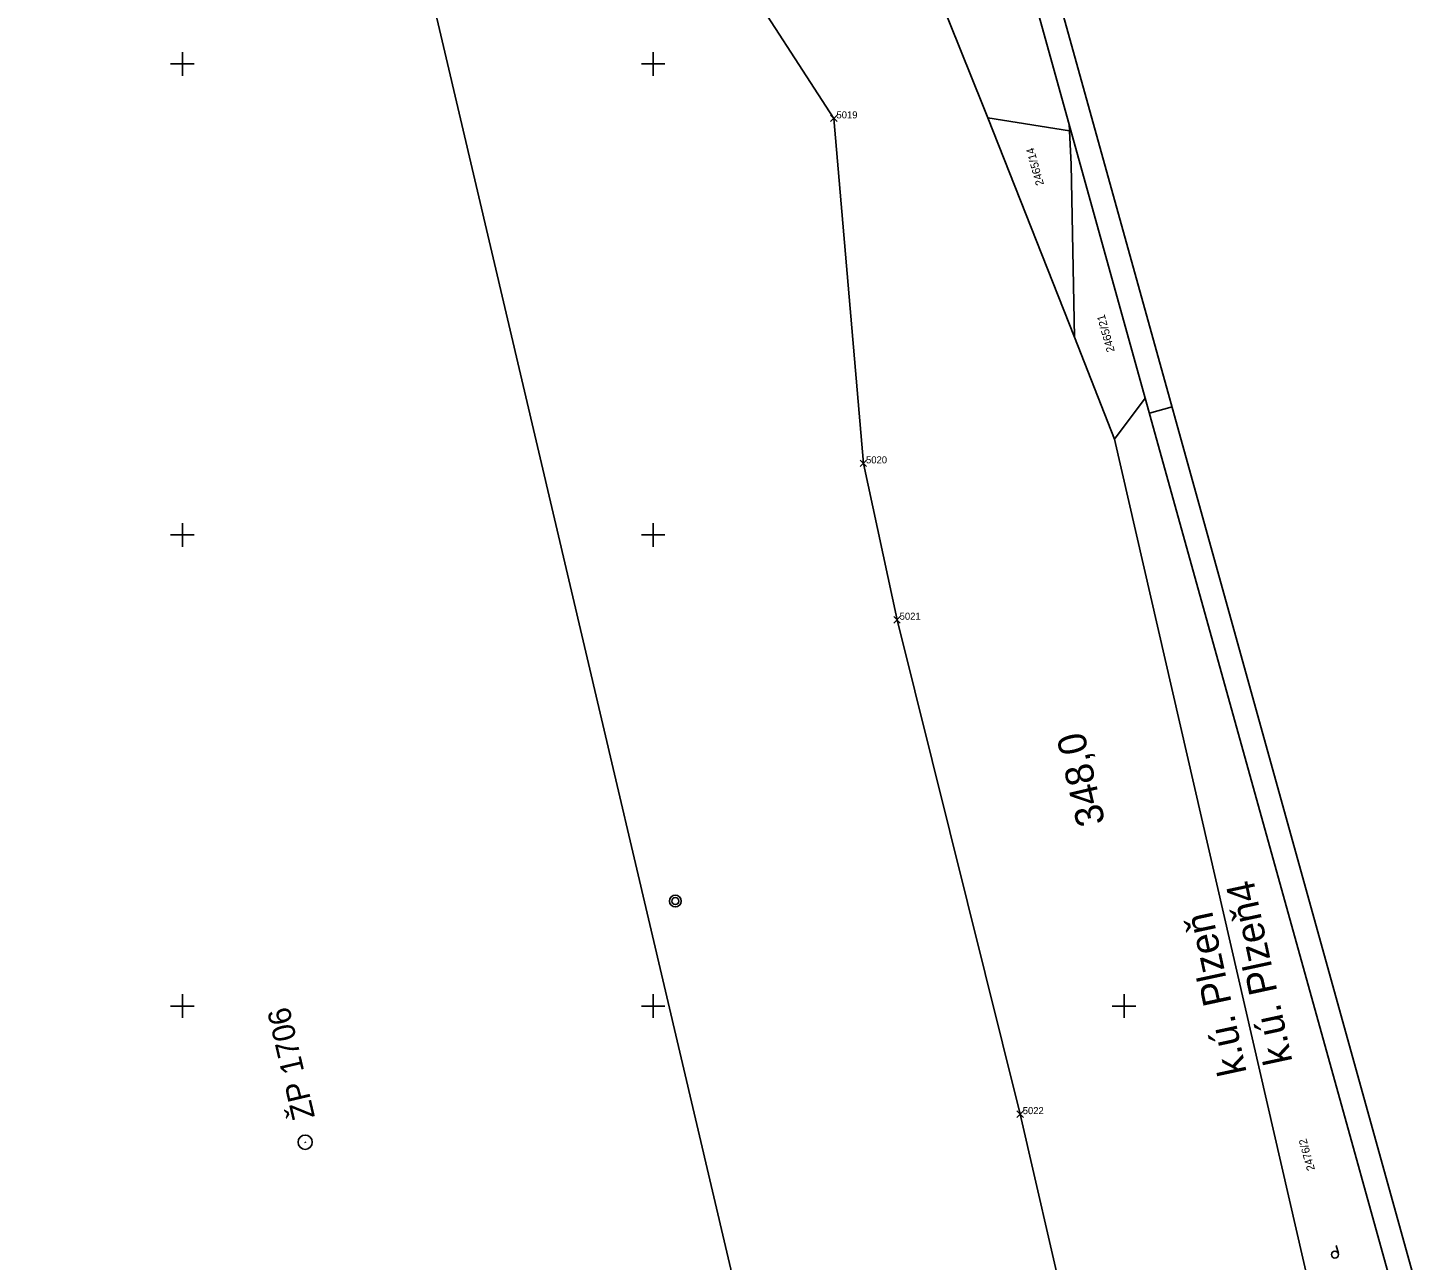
# Model space of a CAD drawing. Extents: x -821172 to -820632, y -1070921 to -1069931.
# Drawn here: x -820866.4 to -820719.1, y -1070527 to -1070396.2 of the extents above; entities that cross this region are included whole.
import ezdxf

# ---------------------------------------------------------------- set-up
doc = ezdxf.new("R2010")
doc.units = 0
for name, color, linetype in [('Ram', 7, 'Continuous'), ('Sit', 7, 'Continuous'), ('Sttaniceni a namezniky', 7, 'Continuous'), ('VB_bod_DZ', 7, 'Continuous'), ('Vrstva 52', 7, 'Continuous'), ('Vrstva 53', 7, 'Continuous'), ('Vrstva 55', 7, 'Continuous'), ('Vrstva 57', 7, 'Continuous'), ('Vrstva 59', 7, 'Continuous'), ('ZBP', 7, 'Continuous')]:
    doc.layers.add(name, color=color, linetype=linetype)

msp = doc.modelspace()

# ---------------------------------------------------------------- linework, layer by layer
at = {"layer": 'Ram'}
msp.add_line((-820744.9, -1070436.39), (-820747.31, -1070437.06), dxfattribs=at)
for points in [[(-820857.35, -1070031.72), (-820632.46, -1070841.06)], [(-820859.09, -1070034.8), (-820635.54, -1070839.32), (-820916.88, -1070917.49)]]:
    msp.add_lwpolyline(points, dxfattribs=at)
at = {"layer": 'Sit'}
for p, q in [((-820850, -1070398.75), (-820850, -1070400)), ((-820800, -1070398.75), (-820800, -1070400)), ((-820851.25, -1070400), (-820850, -1070400)), ((-820848.75, -1070400), (-820850, -1070400)), ((-820850, -1070401.25), (-820850, -1070400)), ((-820801.25, -1070400), (-820800, -1070400)), ((-820798.75, -1070400), (-820800, -1070400)), ((-820800, -1070401.25), (-820800, -1070400)), ((-820850, -1070448.75), (-820850, -1070450)), ((-820800, -1070448.75), (-820800, -1070450)), ((-820851.25, -1070450), (-820850, -1070450)), ((-820848.75, -1070450), (-820850, -1070450)), ((-820850, -1070451.25), (-820850, -1070450)), ((-820801.25, -1070450), (-820800, -1070450)), ((-820798.75, -1070450), (-820800, -1070450)), ((-820800, -1070451.25), (-820800, -1070450)), ((-820850, -1070498.75), (-820850, -1070500)), ((-820800, -1070498.75), (-820800, -1070500)), ((-820750, -1070498.75), (-820750, -1070500)), ((-820851.25, -1070500), (-820850, -1070500)), ((-820848.75, -1070500), (-820850, -1070500)), ((-820850, -1070501.25), (-820850, -1070500)), ((-820801.25, -1070500), (-820800, -1070500)), ((-820798.75, -1070500), (-820800, -1070500)), ((-820800, -1070501.25), (-820800, -1070500)), ((-820751.25, -1070500), (-820750, -1070500)), ((-820748.75, -1070500), (-820750, -1070500)), ((-820750, -1070501.25), (-820750, -1070500))]:
    msp.add_line(p, q, dxfattribs=at)
at = {"layer": 'Sttaniceni a namezniky'}
for radius in [0.623, 0.376]:
    msp.add_circle((-820797.65, -1070488.86), radius, dxfattribs=at)
at = {"layer": 'VB_bod_DZ'}
for p, q in [((-820781.17, -1070406.12), (-820780.48, -1070405.43)), ((-820780.48, -1070406.12), (-820781.17, -1070405.43)), ((-820778.03, -1070442.74), (-820777.34, -1070442.05)), ((-820777.34, -1070442.74), (-820778.03, -1070442.05)), ((-820774.45, -1070459.35), (-820773.76, -1070458.66)), ((-820773.76, -1070459.35), (-820774.45, -1070458.66)), ((-820761.38, -1070511.82), (-820760.69, -1070511.13)), ((-820760.69, -1070511.82), (-820761.38, -1070511.13))]:
    msp.add_line(p, q, dxfattribs=at)
at = {"layer": 'Vrstva 52'}
for points in [[(-820791.18, -1070389.77), (-820780.82, -1070405.78), (-820777.68, -1070442.4), (-820774.11, -1070459), (-820761.04, -1070511.47), (-820756.27, -1070532.22), (-820758.47, -1070564.86)], [(-820782.06, -1070569.19), (-820823.93, -1070391.03)]]:
    msp.add_lwpolyline(points, dxfattribs=at)
at = {"layer": 'Vrstva 53'}
for p, q in [((-820780.16, -1070366.62), (-820765.05, -1070404.29)), ((-820765.05, -1070404.29), (-820764.48, -1070405.73)), ((-820764.48, -1070405.73), (-820755.27, -1070429)), ((-820755.27, -1070429), (-820751, -1070439.83)), ((-820751, -1070439.83), (-820721.42, -1070568.42))]:
    msp.add_line(p, q, dxfattribs=at)
at = {"layer": 'Vrstva 55'}
for p, q in [((-820765.05, -1070404.29), (-820780.16, -1070366.62)), ((-820764.48, -1070405.73), (-820765.05, -1070404.29)), ((-820755.27, -1070429), (-820764.48, -1070405.73)), ((-820764.48, -1070405.73), (-820755.8, -1070407.09)), ((-820755.8, -1070407.09), (-820755.83, -1070406.39)), ((-820751, -1070439.83), (-820755.27, -1070429)), ((-820751, -1070439.83), (-820747.75, -1070435.47)), ((-820721.42, -1070568.42), (-820751, -1070439.83))]:
    msp.add_line(p, q, dxfattribs=at)
msp.add_lwpolyline([(-820755.27, -1070429), (-820755.62, -1070410.67), (-820755.8, -1070407.09)], dxfattribs=at)
at = {"layer": 'Vrstva 59'}
msp.add_line((-820727.24, -1070526.29), (-820727.47, -1070525.44), dxfattribs=at)
msp.add_circle((-820727.61, -1070526.39), 0.375, dxfattribs=at)
at = {"layer": 'ZBP'}
msp.add_line((-820836.94, -1070514.51), (-820836.97, -1070514.41), dxfattribs=at)
msp.add_circle((-820836.96, -1070514.46), 0.756, dxfattribs=at)

# ---------------------------------------------------------------- texts
at = {"layer": 'Sttaniceni a namezniky'}
msp.add_text('348,0', height=3, rotation=103.1705, dxfattribs=at).set_placement((-820751.99, -1070480.53))
at = {"layer": 'VB_bod_DZ'}
for s, p in [(' 5019', (-820780.82, -1070405.78)), (' 5020', (-820777.68, -1070442.4)), (' 5021', (-820774.11, -1070459)), (' 5022', (-820761.04, -1070511.48))]:
    msp.add_text(s, height=0.75, dxfattribs=at).set_placement(p)
at = {"layer": 'Vrstva 57'}
for s, height, rotation, p in [('2465/14', 0.85, 105.5289, (-820758.5, -1070412.78)), ('2465/21', 0.85, 105.5289, (-820750.98, -1070430.48)), ('k.ú. Plzeň4', 3, 102.1429, (-820732.11, -1070505.89)), ('k.ú. Plzeň', 3, 102.1429, (-820736.97, -1070507.06)), ('2476/2', 0.85, 105.5289, (-820729.72, -1070517.36))]:
    msp.add_text(s, height=height, rotation=rotation, dxfattribs=at).set_placement(p)
at = {"layer": 'ZBP'}
msp.add_text('ŽP 1706', height=2.4, rotation=103.1705, dxfattribs=at).set_placement((-820835.91, -1070511.78))

doc.saveas('drawing.dxf')
